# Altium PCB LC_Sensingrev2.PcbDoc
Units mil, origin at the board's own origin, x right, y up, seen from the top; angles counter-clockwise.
Board outline 1000 x 820 mil, 2 copper layers (Top Layer, Bottom Layer), stack 40 mil thick; 60 components, 18 nets, 111 pads, 7 vias.
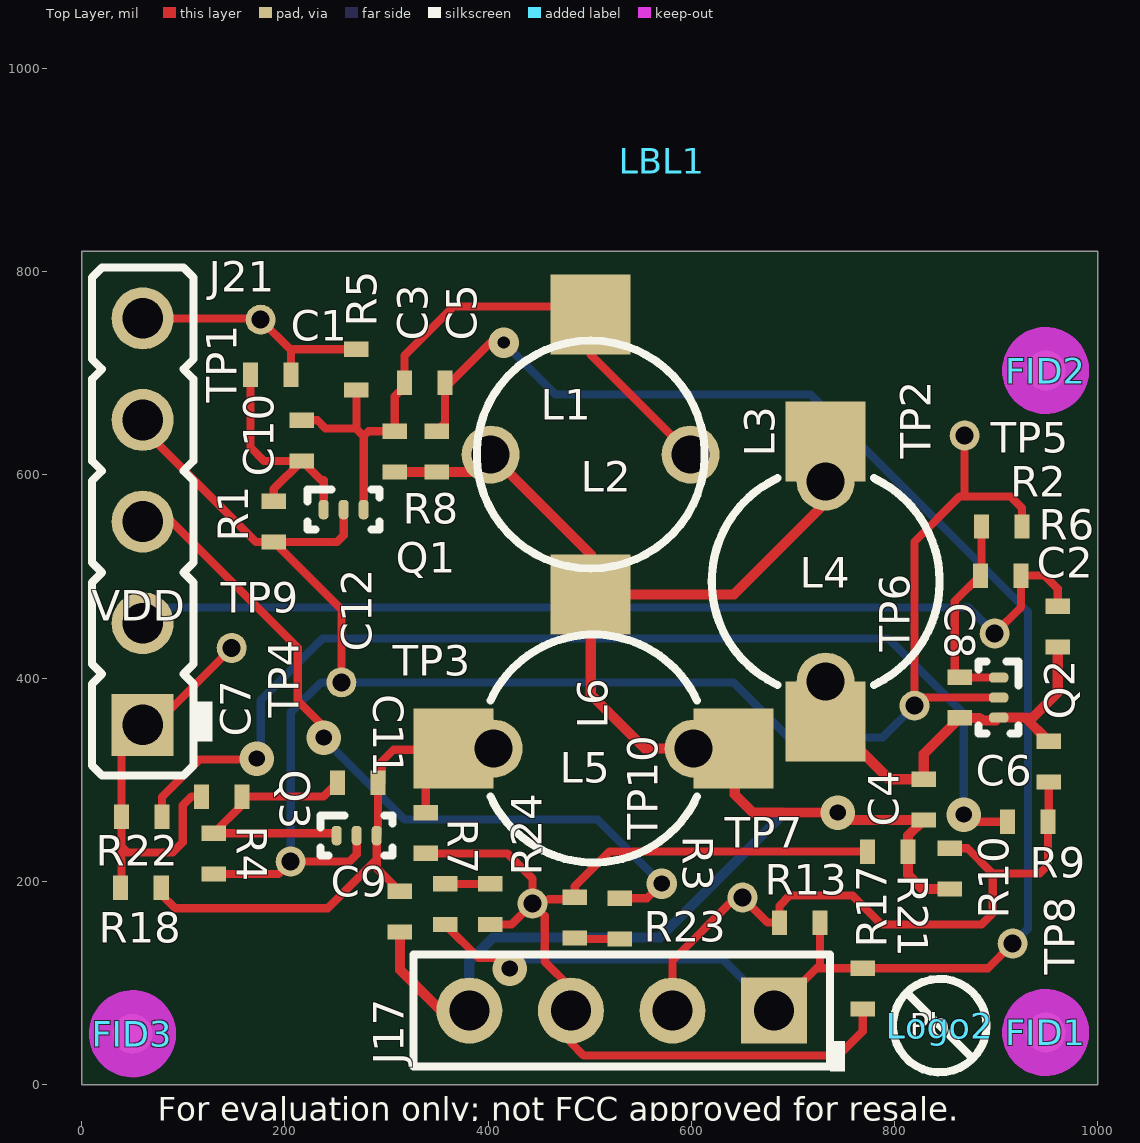
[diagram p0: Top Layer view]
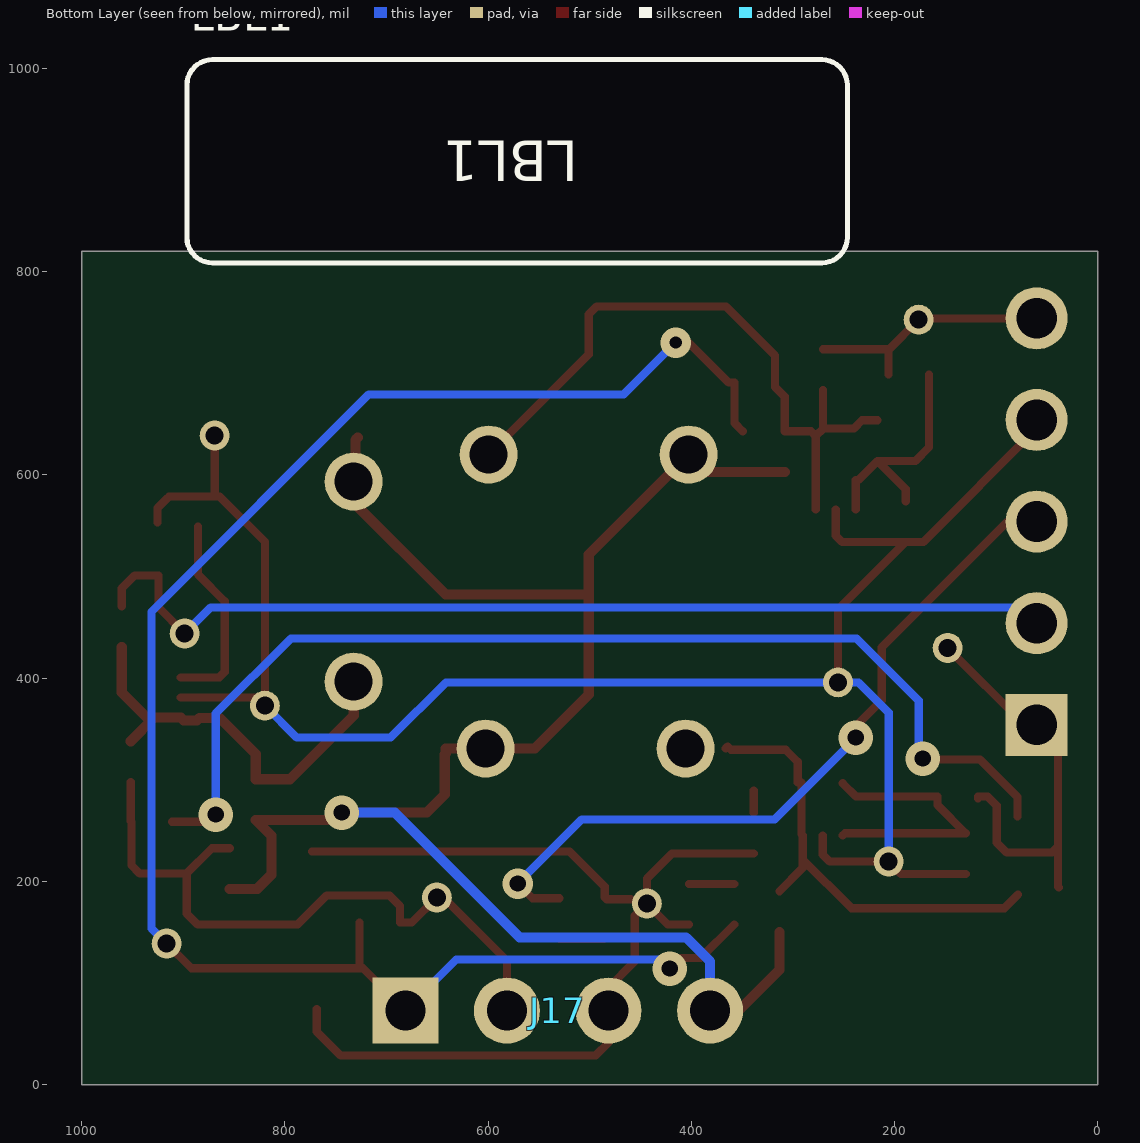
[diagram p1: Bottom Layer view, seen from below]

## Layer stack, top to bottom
Top Solder: solder mask 0.4, Solder Resist, Dk 3.5
Top Layer: signal copper 1.4
Dielectric1: core 37.2, FR-4, Dk 4.8
Bottom Layer: signal copper 1.4
Bottom Solder: solder mask 0.4, Solder Resist, Dk 3.5

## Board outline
0,0 1000,0 1000,820 0,820

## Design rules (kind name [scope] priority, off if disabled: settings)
AcuteAngle [All] p1: minimum=4.50000000000000E+0001 checktracksonly=FALSE
AssemblyTestPointUsage [All] p1: valid=2
BoardOutlineClearance BoardOutlineClearance_MountingHoles [OnCopper and InComponentClass('Mounting Holes')] p1: gap=20
BoardOutlineClearance BoardOutlineClearance_Poly [OnCopper and IsPoly] p2: gap=20
BoardOutlineClearance [OnCopper and Not InComponentClass('Logo') and not InComponentClass('FiducialMark') and not InRegion(1000,500,4000,800) and not InPoly] p3: gap=22
Clearance Clearance_Keepouts [((IsTrack Or IsArc) And Not InPoly) And IsFree and IsKeepOut vs ((IsTrack Or IsArc) And Not InPoly) And IsFree and IsKeepOut] p1: gap=0
Clearance Clearance_Poly [InPolygon] p2: gap=25
Clearance [All] p3: gap=7.87
ComponentClearance ComponentClearance_MountingHoles_FiducialMarks [InComponentClass('Mounting Holes') vs InComponentClass('FiducialMark')] p1: gap=3.94 collisioncheckmode=3 verticalgap=3.94 showdistances=FALSE
ComponentClearance ComponentClearance_Shunt [InComponentClass('Header') vs InComponentClass('Shunt')] p2: gap=0 collisioncheckmode=3 verticalgap=0 showdistances=FALSE
ComponentClearance ComponentClearance_Logo [InComponentClass('Logo')] p3: gap=10 collisioncheckmode=3 verticalgap=10 showdistances=TRUE
ComponentClearance ComponentClearance_ScrewToNut [(HasFootprint('NY PMS 440 0025 PH')) vs (HasFootprint('Keystone_1902C'))] p4: gap=5 collisioncheckmode=3 verticalgap=10 showdistances=FALSE
ComponentClearance ComponentClearance_MountingHoles [InComponentClass('Mounting Holes')] p5: gap=250 collisioncheckmode=3 verticalgap=100000 showdistances=FALSE
ComponentClearance ComponentClearance_SmallPassives [HasFootprint('0201*') or HasFootprint('0402*') or HasFootprint('0508') or HasFootprint('0603*') or HasFootprint('0612') or HasFootprint('0805*') or HasFootprint('0815*') or HasFootprint('0830*') or HasFootprint('1206*') or HasFootprint('1210*') or HasFootprint('1808*') or HasFootprint('1812*') or HasFootprint('1825*') or HasFootprint('2010*') or HasFootprint('2220*') or HasFootprint('2225*') or HasFootprint('2512*') or HasFootprint('2728*') or HasFootprint('3518*') vs HasFootprint('0201*') or HasFootprint('0402*') or HasFootprint('0508') or HasFootprint('0603*') or HasFootprint('0612') or HasFootprint('0805*') or HasFootprint('0815*') or HasFootprint('0830*') or HasFootprint('1206*') or HasFootprint('1210*') or HasFootprint('1808*') or HasFootprint('1812*') or HasFootprint('1825*') or HasFootprint('2010*') or HasFootprint('2220*') or HasFootprint('2225*') or HasFootprint('2512*') or HasFootprint('2728*') or HasFootprint('3518*')] p6: gap=14.96 collisioncheckmode=3 verticalgap=10 showdistances=FALSE
ComponentClearance ComponentClearance_THtoSMT [IsThruComponent vs IsSMTComponent] p7: gap=10 collisioncheckmode=3 verticalgap=10 showdistances=FALSE
ComponentClearance ComponentClearance_THtoTH [IsThruComponent vs IsThruComponent] p8: gap=12 collisioncheckmode=3 verticalgap=12 showdistances=FALSE
ComponentClearance [All] p9: gap=7 collisioncheckmode=3 verticalgap=7 showdistances=FALSE
DiffPairsRouting [All] p1: maxlimit=100 minlimit=10 mostfreqgap=10 toplayer_minwidth=15 toplayer_maxwidth=15 toplayer_prefwidth=15 bottomlayer_minwidth=15 bottomlayer_maxwidth=15 bottomlayer_prefwidth=15 maxuncoupledlength=1000
FabricationTestPointUsage TestPointUsage [All] p1: valid=2 allowmultiple=FALSE
FabricationTestpoint Testpoint [All] p1: side=3 testpointundercomponent=TRUE minsize=40 maxsize=100 preferedsize=60 minholesize=0 maxholesize=40 preferedholesize=32 testpointgrid=1 allowsidetop=TRUE allowsidebottom=TRUE usegrid=TRUE gridtolerance=0.01
FanoutControl Fanout_LCC [IsLCC] p1: bgadir=Out bgaviamode=Centered fanoutstyle=Auto fanoutdirection=Alternating viagrid=1 // Fanout_LCC (Default Rule)
FanoutControl Fanout_BGA [IsBGA] p2: bgadir=Out bgaviamode=Centered fanoutstyle=Auto fanoutdirection=Alternating viagrid=1 // Fanout_BGA (Default Rule)
FanoutControl Fanout_Default [All] p4: bgadir=Out bgaviamode=Centered fanoutstyle=Auto fanoutdirection=Alternating viagrid=1 // Fanout_Default (Default Rule)
FanoutControl Fanout_Small [(CompPinCount < 5)] p5: bgadir=Out bgaviamode=Centered fanoutstyle=Auto fanoutdirection=OutThenIn viagrid=1 // Fanout_Small (Default Rule)
HoleSize [All] p1: absolutevalues=TRUE maxlimit=251 minlimit=7.87 maxpercent=80.000 minpercent=20.000
MinimumAnnularRing MinimumAnnularRing_ThermalPadVias [IsVia and InAnyComponent] p1: minimumring=5.91
MinimumAnnularRing [All] p2: minimumring=5.91
MinimumSolderMaskSliver MinimumSolderMaskSliver_Logo [InComponentClass('Logo') vs InComponentClass('Logo')] p1: minsoldermaskwidth=0.7
MinimumSolderMaskSliver [All] p2: minsoldermaskwidth=3.94
PlaneConnect [All] p1: planeconnectstyle=Relief reliefexpansion=10 reliefentries=4 reliefconductorwidth=10 reliefairgap=10
PolygonConnect [All] p1: connectstyle=Relief reliefconductorwidth=10 reliefentries=4 polygonreliefangle="90 Angle" airgapwidth=10
RoutingVias ThermalPadVias [IsVia and InAnyComponent] p1: holewidth=7.87 width=19.68 viastyle="Through Hole" minholewidth=7.87 minwidth=19.68 maxholewidth=12.99 maxwidth=23.62
RoutingVias [All] p2: holewidth=16 width=34 viastyle="Through Hole" minholewidth=7.87 minwidth=26 maxholewidth=40 maxwidth=65
SilkToBoardRegionClearance [Not ((IsComment or IsDesignator) And (Hide <> 'False')) and not InRegion(1000,500,4000,800)] p1:
SilkToSilkClearance SilkToSilkClearance_Pb-FreeLogo [(HasFootprint('Pb-Free_Overlay_Medium') OR HasFootprint('Pb-Free_Overlay_Small')) vs (HasFootprint('Pb-Free_Overlay_Medium') OR HasFootprint('Pb-Free_Overlay_Small'))] p1: silktosilkclearance=0
SilkToSilkClearance [All] p2: silktosilkclearance=2
SilkToSolderMaskClearance SilkToComponentPadClearance [IsPad and InAnycomponent] p1: minsilkscreentomaskgap=5 clearancetoexposedcopper=TRUE
SilkToSolderMaskClearance "Silk to Solder Mask Opening" [All] p2: minsilkscreentomaskgap=4 clearancetoexposedcopper=FALSE
SolderMaskExpansion [All] p1: expansion=1.97
UnRoutedNet [All] p1 off:
Width [All] p1: maxlimit=100 minlimit=6 preferedwidth=10 checkconnectedcopper=TRUE
14 further rules are at their usual default settings.

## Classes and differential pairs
component class LC_PMOSrev2: C1 C2 C3 C4 C5 C6 C7 C8 C9 C10 C11 C12 J17 J21 L1 L2 L3 L4 L5 L6 Q1 Q2 Q3 R1 R2 R3 R4 R5 R6 R7 R8 R9 R10 R13 R17 R18 R21 R22 R23 R24 TP1 TP2 TP3 TP4 TP5 TP6 TP7 TP8 TP9 TP10
component class Label: LBL1
component class AssemblyNote: ZZ1 ZZ2 ZZ3 ZZ4
component class FiducialMark: FID1 FID2 FID3
component class LC_Hardwarerev2: FID1 FID2 FID3 LBL1 Logo2 Logo3 ZZ1 ZZ2 ZZ3 ZZ4
component class Header: J17 J21

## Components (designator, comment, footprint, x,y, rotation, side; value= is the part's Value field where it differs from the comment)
C1 "GRM155R61A473KA01D" 0402S 186.02,698.82 r0 top
C2 "GRM155R61A473KA01D" 0402S 904.53,500.98 r0 top
C3 "GRM1555C1H101JA01D" 0402S 308.07,623.03 r270 top
C4 "GRM1555C1H101JA01D" 0402S 828.74,280.51 r270 top
C5 "GRM1555C1H101JA01D" 0402S 337.6,690.94 r180 top
C6 "GRM1555C1H101JA01D" 0402S 951.77,317.91 r90 top
C7 "GRM155R61A473KA01D" 0402S 137.8,283.46 r180 top
C8 "GRM155R71H332KA01D" 0402S 864.42,380.95 r270 top
C9 "GRM1555C1H101JA01D" 0402S 313.23,170.28 r270 top
C10 "GRM155R71H332KA01D" 0402S 216.67,633.86 r90 top
C11 "GRM1555C1H101JA01D" 0402S 338.58,247.58 r90 top
C12 "GRM155R71H332KA01D" 0402S 271.65,297.24 r0 top
FID1 "Fiducial" Fiducial10-20 948.82,51.18 r0 top
FID2 "Fiducial" Fiducial10-20 948.82,702.76 r0 top
FID3 "Fiducial" Fiducial10-20 50,50 r0 top
J17 "PEC04SAAN" SULLINS_PEC04SAAN 531.5,72.83 r180 bottom locked
J21 "PEC05SAAN" Sullins_PxC05SAAN 60.04,554.13 r90 top locked
L1 "BV1935" BV1935 500.98,620.08 r90 top
L2 "BV1935" BV1935 732.29,495.08 r270 top
L3 "GT1128-0" GT1128-0 500.98,620.08 r0 top
L4 "GT1128-0" GT1128-0 732.29,495.07 r270 top
L5 "GT1128-0" GT1128-0 503.94,330.71 r180 top
L6 "BV1935" BV1935 503.94,330.71 r180 top
LBL1 "Size: 0.65\" x 0.20 \"" Label_650x200 571.44,908.73 r0 top
Logo2 "Pb-Free Symbol" Pb-Free_Overlay_Small 844.49,58.07 r0 top
Logo3 "FCC disclaimer" FCC_disclaimer 2350,3380 r0 top
Q1 "CSD23285F5" YJK0003A 257.87,565.94 r0 top
Q2 "CSD23285F5" YJK0003A 902.56,380.91 r270 top
Q3 "CSD23285F5" YJK0003A 270.67,245.08 r0 top
R1 "CRCW04021M00JNED" 0402S 188.98,554.13 r270 top
R2 "CRCW04021M00JNED" 0402S 905.51,549.21 r0 top
R3 "CRCW04021M00JNED" 0402S 485.24,164.37 r270 top
R4 "CRCW04021M00JNED" 0402S 129.92,227.36 r270 top
R5 "CRCW04020000Z0ED" 0402S 270.4,703.74 r90 top
R6 "CRCW04020000Z0ED" 0402S 960.63,450.79 r90 top
R7 "CRCW04021M00JNED" 0402S 357.73,177.58 r90 top
R8 "CRCW04021M20JNED" 0402S 349.41,623.03 r90 top
R9 "CRCW04021M00JNED" 0402S 931.1,258.71 r180 top
R10 "CRCW04021M20JNED" 0402S 854.33,212.6 r90 top
R13 "CRCW04020000Z0ED" 0402S 706.69,159.45 r180 top
R17 "CRCW04020000Z0ED" 0402S 768.7,94.49 r270 top
R18 "CRCW04020000Z0ED" 0402S 58.27,193.9 r180 top
R21 "CRCW04021M20JNED" 0402S 793.31,229.33 r180 top
R22 "CRCW04020000Z0ED" 0402S 59.06,263.78 r0 top
R23 "CRCW04020000Z0ED" 0402S 529.73,163.39 r270 top
R24 "CRCW04020000Z0ED" 0402S 402.22,177.58 r90 top
TP1 "TP_H0.45P0.75" TP_H045P075#1 214.57,487.2 r90 top
TP2 "TP_H0.45P0.75" TP_H045P075#2 898.62,443.9 r90 top
TP3 "TP_H0.45P0.75" TP_H045P075#3 275.59,695.87 r90 top
TP4 "TP_H0.45P0.75" TP_H045P075#2 205.71,219.49 r90 top
TP5 "TP_H0.45P0.75" TP_H045P075#2 869.08,638.78 r90 top
TP6 "TP_H0.45P0.75" TP_H045P075#2 819.72,372.87 r90 top
TP7 "TP_H0.45P0.75" TP_H045P075#2 650.48,184.06 r90 top
TP8 "TP_H0.45P0.75" TP_H045P075#2 916.34,138.78 r90 top
TP9 "TP_H0.45P0.75" TP_H045P075#4 147.68,449.8 r90 top
TP10 "TP_H0.45P0.75" TP_H045P075#2 443.73,178.15 r90 top
ZZ1 "This Assembly Note is for PCB labels only" AssemblyNoteLabel 185,3938 r0 top
ZZ2 "These assemblies are ESD sensitive, ESD precautions shall be observed." AssemblyNote 185,3829.11 r0 top
ZZ3 "These assemblies must be clean and free from flux and all contaminants. Use of no clean flux is not acceptable." AssemblyNote 185,3740.56 r0 top
ZZ4 "These assemblies must comply with workmanship standards IPC-A-610 Class 2, unless otherwise specified." AssemblyNote 185,3652 r0 top

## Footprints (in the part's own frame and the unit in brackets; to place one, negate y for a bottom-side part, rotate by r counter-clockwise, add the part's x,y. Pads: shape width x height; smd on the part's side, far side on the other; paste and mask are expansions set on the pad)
0402S [mil] "Based on C0402S footprint from PADS legacy"
  rect 15x24 smd: 1(-20,0) 2(20,0)
  body extent -22,-12 22,12, height 24
AssemblyNote [mil] "Assembly Note"
AssemblyNoteLabel [mil] "Assembly Note for PCB Labels"
BV1935 [mm] "SMD, 2-Leads, Dia 5.7mm"
  rect 2x2 smd: 1(-3.5,0) 2(3.5,0)
  silkscreen extent -2.52,-2.85 2.52,2.85, body extent -2.85,-2.85 2.85,2.85, height 4.7
FCC_disclaimer [mil]
Fiducial10-20 [mm]
  round 1 smd mask+0.5: 1(0,0)
  Top Layer keep-out circle w1.178: c0,0 r0.5
GT1128-0 [mm] "TH, 2-Leads, Body 6.4x5.7mm, Pin Spacing 5mm"
  round 1.45 hole 0.95: 1(-2.5,0) 2(2.5,0)
  silkscreen extent -2.58,-2.85 2.58,2.85, body extent -2.85,-2.85 2.85,2.85, height 6.2
Label_650x200 [mil] "Thermal Transfer Label"
  round 1 on Mech14: 0(0,0)
  body extent -325,-100 325,100, height 1
Pb-Free_Overlay_Small [mil]
  silkscreen extent -46,-46 46,46
SULLINS_PEC04SAAN [mm] "SULLINS"
  rect 1.65x1.65 hole 1: 1(-3.81,0)
  round 1.65 hole 1: 2(-1.27,0) 3(1.27,0) 4(3.81,0)
  body extent -5.21,-1.33 5.21,1.33, height 8.38
Sullins_PxC05SAAN [mm] "Header, 2.54mm, 5x1, TH"
  rect 1.55x1.55 hole 1.016: 1(-5.08,0)
  round 1.55 hole 1.016: 2(-2.54,0) 3(0,0) 4(2.54,0) 5(5.08,0)
  silkscreen extent -6.35,-1.75 6.35,1.27, body extent -6.35,-1.27 6.35,1.27, height 5.84
TP_H045P075#1 [mm] "TP_H0.45P0.75"
  round 0.75 hole 0.45: 1(6.746,0.975)
TP_H045P075#2 [mm] "TP_H0.45P0.75"
  round 0.75 hole 0.45: 1(0,0)
TP_H045P075#3 [mm] "TP_H0.45P0.75"
  round 0.75 hole 0.45: 1(-7.62,0.508)
TP_H045P075#4 [mm] "TP_H0.45P0.75"
  round 0.75 hole 0.45: 1(-0.508,0)
YJK0003A [mm] "SMD, 3-Leads, Body 1.49x0.73mm"
  rrect50% 0.2x0.39 on Top Paste: 1(-0.525,0) 2(0,0) 3(0.525,0)
  rrect80% 0.25x0.49 smd paste-0.15 mask-0.05: 1(-0.5,0) 2(0,0) 3(0.5,0)
  silkscreen extent -0.9,-0.5 0.9,0.5, body extent -0.75,-0.37 0.74,0.36, height 0.35

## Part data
C1 C2 C7: "CAP, CERM, 0.047 µF, 10 V, +/- 10%, X5R, 0402"
C3 C4 C5 C6 C9 C11: "CAP, CERM, 100 pF, 50 V, +/- 5%, C0G/NP0, 0402"
C8 C10 C12: "CAP, CERM, 3300 pF, 50 V, +/- 10%, X7R, 0402"
FID1 FID2 FID3: "Fiducial mark.  There is nothing to buy or mount."
J17: "Header, 100mil, 4x1, Tin, TH"
J21: "Header, 2.54mm, 5x1, Tin, TH"
L1 L2 L6: "Inductor, Wirewound, 200 µH, 1.9 ohm, SMD"
L3 L4 L5: "Inductor, 235µH, TH"
LBL1: library part THT-14-423-10, "Thermal Transfer Printable Labels, 0.650\" W x 0.200\" H - 10,000 per roll"
Logo2: library part Pb-Free
Logo3: library part FCC_disclaimer, "FCC_disclaimer"
Q1 Q2 Q3: "MOSFET, P-CH, -12 V, -3.3 A, YJK0003A (PICOSTAR-3)"
R1 R2 R3 R4 R7 R9: "RES, 1.0 M, 5%, 0.063 W, 0402"
R5 R6 R13 R17 R18 R22 R23 R24: "RES, 0, 5%, 0.063 W, 0402"
R8 R10 R21: "RES, 1.2 M, 5%, 0.063 W, 0402"
TP1 TP2 TP3 TP4 TP5 TP6 TP7 TP8 TP9 TP10: "Testpoint"
ZZ1: library part AssemblyNoteLabel
ZZ2 ZZ3 ZZ4: library part AssemblyNote

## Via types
v1: diameter 34, hole 16, Top Layer to Bottom Layer, 5 vias
v2: diameter 30, hole 16, Top Layer to Bottom Layer, 1 vias
v3: diameter 30, hole 12, Top Layer to Bottom Layer, 1 vias

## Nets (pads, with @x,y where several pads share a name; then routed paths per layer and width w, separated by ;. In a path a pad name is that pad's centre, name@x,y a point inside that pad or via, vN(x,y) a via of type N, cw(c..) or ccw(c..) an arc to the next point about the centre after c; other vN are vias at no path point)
BIAS1: R7.2 R24.2 | length 44.5
  Top Layer w8: R7.2 R24.2
BIAS2: R9.2 R22.2 | length 1081.4
  Top Layer w8: R22.2 79.06,282.99 115.95,319.88 v1@172.24,319.88 ; v1@172.24,318.9 v1@172.24,319.88 ; v1@172.24,320.87 v1@172.24,319.88 ; v1(868.11,265.75) 875.15,258.71 R9.2
  Bottom Layer w8: v1(172.25,320.88) 176.18,324.81 176.18,377.95 237.2,438.98 794.17,438.98 868.11,365.04 v1(868.11,265.75)
BIAS3: R3.2 R23.2 | length 43.5
  Top Layer w8: R3.2@486.22,143.39 R23.2
DVDD: J21.4 Q1.2@257.87,565.94 Q2.2@902.56,380.91 Q3.2@270.67,245.08 R1.2 R2.2 R4.2 TP3.1 TP4.1 TP5.1 TP6.1 | length 1873
  Top Layer w8: J21.4 60.04,645.67 171.57,534.13 R1.2 R1.2@189.15,533.96 ; R4.2 193.58,207.36 TP4.1 263.78,219.49 270.67,226.38 Q3.2@270.67,245.08 ; TP3.1 255.59,467.52 R1.2@189.15,533.96 ; Q1.2@257.87,565.94 257.87,540.35 251.48,533.96 R1.2@189.15,533.96 ; TP6.1@820.87,363.19 TP6.1@825.14,367.46 ; 869.08,583.65 TP5.1 ; Q2.2@902.56,380.91 827.76,380.91 TP6.1 819.72,534.29 864.17,578.74 914.12,578.74 ; 915.72,577.14 925.51,567.35 R2.2@925.51,553.15
  Bottom Layer w8: TP4.1 205.71,366.14 235.43,395.87 TP3.1 641.54,395.87 695.87,341.54 788.39,341.54 TP6.1 ; TP6.1@819.72,382.87 TP6.1@820.87,382.87
FLOW_OUTP: C5.1 J17.1 R7.1 R8.2 R13.1 R17.1 TP8.1 | length 1743.5
  Top Layer w8: R8.2 357.6,651.22 C5.1 363.19,690.94 402.56,730.32 v3(415.35,730.32) ; R7.1 390.78,124.52 410.94,124.52 v1(421.28,114.18) ; J17.1@690.28,81.62 723.15,114.49 R17.1 892.05,114.49 TP8.1 ; 726.69,118.03 R13.1
  Bottom Layer w8: v3(415.35,730.32) 466.54,679.13 717.52,679.13 931.27,465.38 931.27,153.71 TP8.1 ; v1(421.28,114.18) 421.26,118.11 426.18,123.03 631.3,123.03 J17.1
FLOW_OUTP2: C6.1 J17.2 R9.1 R10.2 R13.2 TP7.1 | length 669.2
  Top Layer w8: J17.2 581.5,121.85 643.7,184.06 TP7.1 675.09,159.45 R13.2 686.69,175.87 696.85,186.02 758.86,186.02 787.4,157.48 885.83,157.48 896.65,168.31 896.65,207.68 ; R10.2 871.73,232.6 896.65,207.68 ; C6.1 951.77,259.38 R9.1 951.1,215.87 942.91,207.68 896.65,207.68
FLOW_OUTP3: C11.1 J17.3 R3.1 R17.2 R21.2 R24.1 TP10.1 | length 1006.7
  Top Layer w8: C11.1 419.08,227.58 443.73,202.92 TP10.1 ; R24.1 423.16,157.58 TP10.1 ; 459.65,182.4 483.27,182.4 R3.1 485.24,194.88 519.69,229.33 R21.2 ; R17.2 768.7,52.17 745.08,28.54 718.95,28.54 718.89,28.48 644.1,28.48 644.04,28.54 599.93,28.54 599.87,28.48 563.13,28.48 563.07,28.54 494.09,28.54 481.5,41.14 J17.3 481.5,95.27 455.71,121.06 455.71,166.17 TP10.1
FLOW_TRIG1: C1.2 J21.5 R5.2 TP1.1 | length 235.9
  Top Layer w8: J21.5@69.88,754.13 174.84,754.13 TP1.1 206.02,722.95 C1.2 ; 207.68,723.74 R5.2
FLOW_TRIG2: C2.2 J21.2 R6.2 TP2.1 | length 982.2
  Top Layer w8: TP2.1 924.53,469.8 C2.2 947.83,500.98 960.63,488.19 R6.2
  Bottom Layer w8: J21.2 75.39,469.49 873.03,469.49 TP2.1
FLOW_TRIG3: C7.2 J21.1 R18.2 R22.1 TP9.1 | length 420.2
  Top Layer w8: R18.2 39.06,194.69 39.06,234.25 ; J21.1@39.06,333.15 R22.1 39.06,234.25 ; J21.1 J21.1@72.01,354.13 ; J21.1@76.65,354.13 J21.1@72.01,354.13 ; C7.2@117.79,281.5 C7.2 108.27,283.47 99.41,274.61 99.41,238.19 89.57,228.35 44.96,228.35 39.06,234.25 ; TP9.1 J21.1@72.01,354.13
  Bottom Layer w8: J21.1@39.06,333.15 J21.1
FLOW_TRIG4: J21.3 R23.1 | length 743
  Top Layer w8: J21.3 88.58,554.13 212.6,430.12 212.6,377.95 238.19,352.36 v1(238.19,341.54) ; R23.1 556.42,183.39 v2(570.87,197.83)
  Bottom Layer w8: v1(238.19,341.54) 238.19,340.55 317.91,260.83 507.87,260.83 v2(570.87,197.83)
GND: C3.2 C4.2 C9.2 J17.4 L1.1 L2.1 L3.1 L4.1 L5.1 L6.1 R8.1 R10.1 R21.1 | length 1817.4
  Top Layer w10: C3.2 R8.1 385.5,603.03 L3.1 500.98,521.66 L1.1 ; C9.2 313.23,112.95 353.35,72.84 J17.4 ; L2.1@728.35,636.81 730.63,634.53 730.63,571.18 641.74,482.29 L1.1 ; R10.1 827.09,192.6 813.31,206.38 R21.1 813.31,245.08 C4.2 751.3,260.51 v1(744.09,267.72) 660.43,267.72 642.72,285.43 642.72,324.8 641.73,325.79 L6.1 554.13,330.71 500.98,383.86 L1.1
  Bottom Layer w10: J17.4 381.5,121.06 405.12,144.68 568.9,144.68 691.93,267.72 v1(744.09,267.72)
NetC1_1: C1.1 C10.1 Q1.1@238.19,565.94 R1.1 | length 237.4
  Top Layer w8: C1.1 166.02,627.28 179.45,613.86 C10.1 ; R1.1 188.98,586.16 C10.1 ; Q1.1@238.19,565.94 238.19,595.12 235.41,595.12 C10.1
NetC2_1: C2.1 C8.1 Q2.1@902.56,400.59 R2.1 | length 199.6
  Top Layer w8: R2.1 885.51,501.97 C2.1 859.25,475.71 859.25,443.9 859.25,406.12 C8.1 864.78,400.59 Q2.1@902.56,400.59
NetC3_1: C3.1 C5.2 C10.2 L1.2 L3.2 Q1.3@277.56,565.94 R5.1 | length 673.2
  Top Layer w8: C10.2 231.97,653.86 239.99,645.84 269.96,645.84 277.56,638.24 ; 270.4,646.28 R5.1 ; Q1.3@277.56,565.94 277.56,638.24 ; L3.2 500.98,718.51 L1.2 493.11,765.75 365.83,765.75 317.6,717.52 C5.2 317.6,686.69 308.07,677.17 C3.1 282.35,643.03 277.56,638.24
NetC4_1: C4.1 C6.2 C8.2 L2.2 L4.2 Q2.3@902.56,361.22 R6.1 | length 417.8
  Top Layer w10: L4.2 732.29,363.19 794.96,300.51 C4.1 828.74,325.28 C8.2 883.81,360.95 886.5,358.27 899.61,358.27 902.56,361.22 928.47,361.22 ; C6.2 928.47,361.22 ; R6.1 960.63,385.83 936.02,361.22 928.47,361.22
NetC7_1: C7.1 C12.1 Q3.1@250.99,245.08 R4.1 | length 268.3
  Top Layer w8: Q3.1@250.99,245.08 248.7,247.36 R4.1 157.79,275.23 C7.1 237.87,283.47 C12.1@250.99,296.58
NetC9_1: C9.1 C11.2 C12.2 L5.2 L6.2 Q3.3@290.36,245.08 R18.1 | length 472.9
  Top Layer w8: R18.1@78.27,187.22 91.9,173.59 242.49,173.59 290.36,221.46 ; Q3.3@290.36,245.08 290.36,221.46 ; Q3.3@291.65,246.38 C12.2 ; C12.2@295.28,297.24 295.28,317.74 307.09,329.56 361.05,329.56 364.17,332.68 L6.2 ; C9.1 290.36,213.15 290.36,221.46 ; C11.2 338.58,289.37
pads on no net: FID1.1 FID2.1 FID3.1 LBL1.0 Q1.1@237.2,565.94 Q1.2@257.87,565.94 Q1.3@278.54,565.94 Q2.1@902.56,401.58 Q2.2@902.56,380.91 Q2.3@902.56,360.24 Q3.1@250,245.08 Q3.2@270.67,245.08 Q3.3@291.34,245.08

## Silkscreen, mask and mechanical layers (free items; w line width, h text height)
Top Overlay:
  text "1" at 739.84,8036.5 h40
  text "2" at 3235.5,8036.5 h40
  text "3" at 5724.84,8036.5 h40
  text "4" at 8231.51,8036.5 h40
  text "5" at 10730.5,8036.5 h40
  text "6" at 13235.5,8036.5 h40
  text "A" at -416.5,6893.5 h40
  text "A" at 14383.5,6893.5 h40
  text "DESIGN INFORMATION" at 12378.02,6201 h40
  text "MIN. TRACK WIDTH:" at 11733.46,6021 h40
  text "8" at 12829.7,6021 h40
  text "MIL" at 12984.46,6021 h40
  text "MIN. CLEARANCE:" at 11733.46,5889 h40
  text "0.2" at 12769.7,5889 h40
  text "mm" at 12984.46,5889 h40
  text "MIN. VIA PAD SIZE:" at 11733.46,5757 h40
  text "24" at 12799.71,5757 h40
  text "MIL" at 12984.46,5757 h40
  text "0.05mm (2MIL)" at 12428.46,5615.29 h40
  text "MINIMUM ANNULAR RING" at 11404.23,5611 h40
  text "EXTERNAL" at 13136.46,5611 h40
  text "PER" at 11604.23,5493 h40
  text "IPC-D-275 CLASS 2 LEVEL C" at 11824.23,5493 h40
  text "MIL, HOLES" at 13312.46,5380.71 h40
  text "+/-" at 12920,5380 h40
  text "+/-" at 13774,5380 h40
  text "REGISTRATION TOLERANCES:" at 11404.23,5375 h40
  text "METAL" at 12604,5375 h40
  text "5" at 13180.2,5375 h40
  text "3" at 14013.2,5375 h40
  text "MIL" at 14129.46,5375 h40
  text "+/-" at 13774,5262 h40
  text "HOLE SIZE TOLERANCE (UNLESS OTHERWISE SPECIFIED):" at 11404.23,5257 h40
  text "3" at 14013.2,5257 h40
  text "MIL" at 14129.46,5257 h40
  text "MATERIAL:" at 11329.46,5047.54 h40
  text "FR-4 High Tg" at 12315.9,4907.21 h40
  text "FR-408" at 11750.46,4898.64 h40
  text "OTHER" at 13238.46,4898.64 h40
  text "X" at 12161,4895 h40
  text "62 MIL (1.6mm) +/-10%" at 12070.56,4735.92 h40
  text "THICKNESS:" at 11404.23,4731.64 h40
  text "X" at 11942.4,4731.64 h40
  text "OTHER" at 13355.46,4731.64 h40
  text "TOLERANCE:" at 11404.23,4573.64 h40
  text "X" at 12243.53,4573.64 h40
  text "ANSI IPC-6012 TYPE 3 CLASS 2" at 12430.48,4573.64 h40
  text "B" at -416.5,4513.5 h40
  text "B" at 14383.5,4513.5 h40
  text "OTHER +/-" at 12430.46,4417.64 h40
  text "BOW & TWIST:" at 11404.23,4260.64 h40
  text "X" at 12243.53,4260.64 h40
  text "ANSI IPC-6012 TYPE 3 CLASS 2" at 12430.48,4260.64 h40
  text "OTHER +/-" at 12430.46,4102.13 h40
  text "DRILLING:" at 11329.46,3963.64 h40
  text "REFERENCE:" at 11404.23,3846.64 h40
  text "X" at 12052.46,3846.64 h40
  text "AS SHOWN" at 12239.46,3846.64 h40
  text "X" at 12953.46,3846.64 h40
  text "NC_DRILL FILES" at 13090.46,3846.64 h40
  text "PTH COPPER THICKNESS:" at 11404.23,3688.64 h40
  text "X" at 12534.46,3688.64 h40
  text "20-30 um" at 12671.46,3688.64 h40
  text "OTHER" at 13388.46,3688.64 h40
  text "BOARD FINISH:" at 11329.46,3529.64 h40
  text "SILKSCREEN:" at 11484.68,3411.64 h40
  text "X" at 12433.46,3411.64 h40
  text "TOP" at 12559.46,3411.64 h40
  text "X" at 12943.46,3411.64 h40
  text "BOTTOM" at 13070.46,3411.64 h40
  text "SILKSCREEN COLOR:" at 11484.68,3244.64 h40
  text "X" at 12432.42,3244.64 h40
  text "WHITE" at 12559.46,3244.64 h40
  text "OTHER" at 13070.46,3244.64 h40
  text "CERTIFICATION:" at 2339.31,3149.74 h40
  text "X" at 12563.42,3085.44 h40
  text "GREEN" at 12690.46,3085.44 h40
  text "OTHER" at 13308.46,3085.44 h40
  text "SOLDER RESIST COLOR:" at 11484.68,3074.64 h40
  text "X" at 2690.82,2915.24 h40
  text "X" at 12563.42,2915.44 h40
  text "MATTE" at 12690.46,2915.44 h40
  text "SEMI-GLOSS" at 13308,2914.8 h40
  text "X" at 3504.87,2755.74 h40
  text "RoHS" at 3641.82,2755.74 h40
  text "IMMERSION GOLD (ENIG)" at 12390.46,2726.92 h40
  text "ENEPIG" at 13728,2723.64 h40
  text "SURFACE FINISH:" at 11329.46,2722.64 h40
  text "X" at 12203.51,2722.64 h40
  text "IMM. TIN/SILVER OR EQUIV" at 11659,2565.64 h40
  text "OTHER" at 13090.46,2565.64 h40
  text "ARRAY/PANEL:" at 11329.46,2386.64 h40
  text "CUT AND TRIM PER M1 BOARD OUTLINE" at 12390.46,2382.35 h40
  text "ADDITIONAL REQUIREMENTS:" at 2339.31,2296.74 h40
  text "N.C. ROUTE" at 12390.46,2230.64 h40
  text "X" at 13069.46,2230.64 h40
  text "V. SCORE" at 13256.46,2230.64 h40
  text "MICROSECTION:" at 2414.08,2181.74 h40
  text "YES" at 3319.82,2181.74 h40
  text "C" at -416.5,2138.5 h40
  text "C" at 14383.5,2138.5 h40
  text "MATERIALS AND WORKMANSHIP FOR ALL PCBS" at 12054.46,2093.64 h40
  text "BARE BOARD ELEC. TEST:" at 2414.08,2022.74 h40
  text "NONE" at 3719.82,2022.74 h40
  text "TO MEET OR EXCEED THE REQUIREMENTS OF:" at 12054.46,1995.64 h40
  text "ANSI IPC-A-600F CLASS ->" at 11819.96,1859.13 h40
  text "X" at 13459.02,1859.13 h40
  text "2" at 13577.96,1859.14 h40
  text "1" at 13262.96,1857.64 h40
  text "3" at 13931.96,1857.64 h40
  text "OTHER" at 13276.36,1699.64 h40
  text "PER ORDER" at 13673.42,1699.64 h40
  text "ALL BOARDS MUST MEET OR EXCEED UL94-V0 REQUIREMENTS." at 11357,1534 h40
  text "PCB MUST BEAR THE UL94V-0 UL REGISTERED MATERIAL ID NUMBER" at 11357,1414 h40
  text "REQUIRED" at 13171.46,969.49 h40
  text "X" at 13044.46,966.64 h40
  text "PER ORDER" at 13763.46,966.64 h40
  text "VDD" at 9.84,456.69 h30
  text "PROJECT TITLE:" at 11343.5,277.5 h40
  text ".PRJ_Title" at 11393.5,144.17 h40
  text "DESIGNED FOR:" at 11343.5,-23.5 h40
  text ".PRJ_Customer" at 11393.5,-163.5 h40
  text "D" at -416.5,-231.5 h40
  text "D" at 14383.5,-231.5 h40
  text "COMPONENTS MARKED 'DNP' SHOULD NOT BE POPULATED." at 1153.5,-318.5 h40
  text "COMPONENTS MARKED 'DNP' SHOULD NOT BE POPULATED." at 6102,-318 h40
  text "FILE NAME:" at 11343.5,-323.5 h40
  text "ASSEMBLY VARIANT:" at 1153,-434 h40
  text ".VariantName" at 2189,-434 h40
  text ".VariantName" at 5058,-434 h40
  text "ASSEMBLY VARIANT:" at 6097,-434 h40
  text ".PCB_File_Name_No_Path" at 11393.5,-443.5 h40
  text "Texas Instruments (TI) and/or its licensors do not warrant the accuracy or completeness of this specification" at 6374,-605.34 h40
  text "ENGINEER:" at 11343.5,-613.5 h40
  text "LAYOUT BY:" at 12848.5,-613.5 h40
  text "PCB VIEWED FROM TOP SIDE" at -228.5,-655.67 h40
  text "ALL ARTWORK VIEWED FROM TOP SIDE" at -228.5,-655.67 h40
  text ".VersionControl_RevNumber" at 1035.5,-656.17 h40
  text "SVN REV:" at 1541.5,-656.17 h40
  text ".PCB_Rev" at 2088,-656.17 h40
  text "BOARD #:" at 2248,-655.67 h40
  text "BOARD #:" at 2248,-655.67 h40
  text "REV:" at 2379.5,-656.17 h40
  text ".PRJ_Number" at 2793.5,-655.67 h40
  text ".PRJ_Number" at 2793.5,-655.67 h40
  text ".PRJ_Number" at 3224,-656.17 h40
  text "REV:" at 3638,-655.67 h40
  text "REV:" at 3638,-655.67 h40
  text "BOARD #:" at 3769.5,-656.17 h40
  text ".PCB_Rev" at 3929.5,-655.67 h40
  text ".PCB_Rev" at 3929.5,-655.67 h40
  text "SVN REV:" at 4476,-655.67 h40
  text "SVN REV:" at 4476,-655.67 h40
  text ".VersionControl_RevNumber" at 4982,-655.67 h40
  text ".VersionControl_RevNumber" at 4982,-655.67 h40
  text "PCB VIEWED FROM BOTTOM SIDE" at 6246,-656.17 h40
  text "or any information contained therein. TI and/or its licensors do not warrant that this design will meet" at 6329.01,-718 h40
  text ".PRJ_Engineer" at 11393.5,-768.49 h40
  text ".PCB_Layout" at 12899,-768.49 h40
  text "the specifications, will be suitable for your application or fit for any particular purpose, or will operate in" at 6329.01,-830.67 h40
  text "LAYER NAME =" at -228.5,-858.49 h40
  text ".Layer_Name" at 577,-858.49 h40
  text ".Layer_Name" at 577,-858.49 h40
  text ".Layer_Name" at 577,-858.49 h40
  text ".Layer_Name" at 577,-858.49 h40
  text ".Layer_Name" at 577,-858.49 h40
  text ".Layer_Name" at 577,-858.49 h40
  text ".Layer_Name" at 577,-858.49 h40
  text ".Layer_Name" at 577,-858.49 h40
  text ".Layer_Name" at 577,-858.49 h40
  text ".Layer_Name" at 577,-858.49 h40
  text ".Layer_Name" at 577,-858.49 h40
  text ".Layer_Name" at 577,-858.49 h40
  text ".Layer_Name" at 577,-858.49 h40
  text ".Layer_Name" at 577,-858.49 h40
  text ".Layer_Name" at 577,-858.49 h40
  text ".Layer_Name" at 577,-858.49 h40
  text ".Layer_Name" at 577,-858.49 h40
  text ".Layer_Name" at 577,-858.49 h40
  text ".Layer_Name" at 577,-858.49 h40
  text ".Layer_Name" at 577,-858.49 h40
  text ".Layer_Name" at 577,-858.49 h40
  text ".Layer_Name" at 577,-858.49 h40
  text ".Layer_Name" at 577,-858.49 h40
  text ".Layer_Name" at 577,-858.49 h40
  text ".Layer_Name" at 577,-858.49 h40
  text ".Layer_Name" at 577,-858.49 h40
  text "TID #:" at 2248,-859 h40
  text "TID #:" at 2248,-859 h40
  text ".TID" at 2793.5,-859 h40
  text ".TID" at 2793.5,-859 h40
  text ".TID" at 3224,-859.5 h40
  text "TID #:" at 3769.5,-859.5 h40
  text "ALTIUM DESIGNER VERSION:" at 12848.5,-923.5 h40
  text "an implementation. TI and/or its licensors do not warrant that the design is production worthy. You should" at 6329.01,-943.33 h40
  text "completely validate and test your design implementation to confirm the system functionality for your application." at 6374,-1056 h40
  text ".print_Scale" at 11393.5,-1056.83 h40
  text ".Application_BuildNumber" at 12899,-1056.83 h40
  text "PLOT NAME =" at -228.5,-1064.34 h40
  text "PLOT NAME =" at -228.5,-1064.34 h40
  text ".plot_File_Name" at 577,-1064.34 h40
  text ".plot_File_Name" at 577,-1064.34 h40
  text "GENERATED    :" at 2250,-1064.34 h40
  text "GENERATED    :" at 2250,-1064.34 h40
  text ".Print_Date" at 3119.5,-1064.34 h40
  text ".Print_Date" at 3119.5,-1064.34 h40
  text ".Print_Time" at 3848.5,-1064.34 h40
  text ".Print_Time" at 3848.5,-1064.34 h40
  text "TEXAS INSTRUMENTS" at 5113,-1064.34 h40
  text "TEXAS INSTRUMENTS" at 5113,-1064.34 h40
  text "TEXAS INSTRUMENTS" at 904.5,-1064.84 h40
  text ".Print_Time" at 2169,-1064.84 h40
  text ".Print_Date" at 2898,-1064.84 h40
  text "GENERATED    :" at 3767.5,-1064.84 h40
  text ".plot_File_Name" at 5440.5,-1064.84 h40
  text "PLOT NAME =" at 6246,-1064.84 h40
  text "1" at 739.84,-1263.5 h40
  text "2" at 3235.5,-1263.5 h40
  text "3" at 5724.84,-1263.5 h40
  text "4" at 8231.51,-1263.5 h40
  text "5" at 10730.5,-1263.5 h40
  text "6" at 13235.5,-1263.5 h40
M1 Board Outline:
  lines w10: 0,3.94 0,820 1000,820 1000,3.94 0,3.94
M2 Board Dimensions:
  rectangle: 125,-400 500,-275
  rectangle: 0,-275 125,-150
  lines w7: 0,-275 1000,-275 ; 125,-400 125,-150 ; 250,-400 250,-150 ; 500,-400 500,-150 ; 750,-400 750,-150 ; 0,-400 0,-150 1000,-150 1000,-400 0,-400
M5 Assembly Top:
  lines w10: -292,-930.17 6308,-930.17 ; -292,-726.83 6310,-726.83 ; -292,-523.5 -292,-1133.5 3713,-1133.5 6310,-1133.5 6310,-523.5 -291.5,-523.5 -291.5,-1133.5 1284,-1133.5 ; 2173,-1133.5 2173,-523.5 ; 3440,-726.83 3440,-523.5 ; 4280,-726.83 4280,-523.5 ; 4902,-1140 4902,-937.17
M6 Assembly Bottom:
  lines w10: -292.5,-727.33 6309.5,-727.33 ; -290.5,-930.67 6309.5,-930.67 ; 1115.5,-1140.5 1115.5,-937.67 ; 1737.5,-727.33 1737.5,-524 ; 2577.5,-727.33 2577.5,-524 ; 3844.5,-1134 3844.5,-524 ; 4733.5,-1134 6309,-1134 6309,-524 -292.5,-524 -292.5,-1134 2304.5,-1134 6309.5,-1134 6309.5,-524
M9 Title Sheet:
  drawing of 57 lines, arcs and shapes, not listed
M10 Fab Notes:
  drawing of 173 lines, arcs and shapes, not listed
M11 Gerber Information:
  lines w10: -292,-930.17 6308,-930.17 ; -292,-726.83 6310,-726.83 ; -292,-523.5 -292,-1133.5 3713,-1133.5 6310,-1133.5 6310,-523.5 -291.5,-523.5 -291.5,-1133.5 1284,-1133.5 ; 2173,-1133.5 2173,-523.5 ; 3440,-726.83 3440,-523.5 ; 4280,-726.83 4280,-523.5 ; 4902,-1140 4902,-937.17
M12 Stackup:
  drawing of 332 lines, arcs and shapes, not listed
  text "Layer" at 6555.03,7744.02 h60
  text "Name" at 6964.94,7744.02 h60
  text "Material" at 7894.68,7744.02 h60
  text "Thickness" at 8754.45,7744.02 h60
  text "Constant" at 9404.29,7744.02 h60
  text "Board Layer Stack" at 9974.15,7744.02 h60
  text "1" at 6555.03,7624.02 h60
  text "Top Overlay" at 6964.94,7624.02 h60
  text "2" at 6555.03,7504.02 h60
  text "Top Solder" at 6964.94,7504.02 h60
  text "Solder Resist" at 7894.68,7504.02 h60
  text "0.40mil" at 8754.45,7504.02 h60
  text "3.5" at 9404.29,7504.02 h60
  text "3" at 6555.03,7384.02 h60
  text "Top Layer" at 6964.94,7384.02 h60
  text "Copper" at 7894.68,7384.02 h60
  text "1.40mil" at 8754.45,7384.02 h60
  text "4" at 6555.03,7264.02 h60
  text "Dielectric1" at 6964.94,7264.02 h60
  text "FR-4" at 7894.68,7264.02 h60
  text "37.20mil" at 8754.45,7264.02 h60
  text "4.8" at 9404.29,7264.02 h60
  text "5" at 6555.03,7144.02 h60
  text "Bottom Layer" at 6964.94,7144.02 h60
  text "Copper" at 7894.68,7144.02 h60
  text "1.40mil" at 8754.45,7144.02 h60
  text "6" at 6555.03,7024.02 h60
  text "Bottom Solder" at 6964.94,7024.02 h60
  text "Solder Resist" at 7894.68,7024.02 h60
  text "0.40mil" at 8754.45,7024.02 h60
  text "3.5" at 9404.29,7024.02 h60
  text "7" at 6555.03,6904.02 h60
  text "Bottom Overlay" at 6964.94,6904.02 h60
Drill Drawing:
  circle w10: c1507.69,651.54 r22.07
  lines w10: 1485.62,232.19 1529.76,232.19 1529.76,276.34 1485.62,276.34 1485.62,232.19 ; 1485.62,331.51 1485.62,342.55 1496.66,353.58 1485.62,364.62 1485.62,375.66 1496.66,375.66 1507.69,364.62 1518.73,375.66 1529.76,375.66 1529.76,364.62 1518.73,353.58 1529.76,342.55 1529.76,331.51 1518.73,331.51 1507.69,342.55 1496.66,331.51 1485.62,331.51 ; 1485.62,474.98 1529.76,474.98 1507.69,430.83 1485.62,474.98 ; 1485.62,541.19 1496.66,541.19 1496.66,530.15 1518.73,530.15 1518.73,541.19 1529.76,541.19 1529.76,563.26 1518.73,563.26 1518.73,574.3 1496.66,574.3 1496.66,563.26 1485.62,563.26 1485.62,541.19 ; 1485.62,739.83 1496.66,739.83 1507.69,728.79 1518.73,739.83 1529.76,739.83 1518.73,750.86 1529.76,761.9 1518.73,761.9 1507.69,772.94 1496.66,761.9 1485.62,761.9 1496.66,750.86 1485.62,739.83
  lines w12: 1444.98,202.4 4556.19,202.4 ; 1444.98,798.32 4556.19,798.32 ; 1760.46,103.08 1760.46,897.64 ; 2077.56,103.08 2077.56,897.64 ; 2699.2,103.08 2699.2,897.64 ; 2943.39,103.08 2943.39,897.64 ; 3303.63,103.08 3303.63,897.64 ; 4012.1,103.08 4012.1,897.64 ; 1444.98,103.08 4556.19,103.08 4556.19,897.64 1444.98,897.64 1444.98,103.08
  text "Symbol" at 1504.57,828.11 h72
  text "Quantity" at 1790.26,828.11 h72
  text "Finished Hole Size" at 2107.35,828.11 h72
  text "Plated" at 2728.99,828.11 h72
  text "Hole Type" at 2973.19,828.11 h72
  text "Drill Layer Pair" at 3333.43,828.11 h72
  text "Hole Tolerance" at 4041.9,828.11 h72
  text "1" at 1790.26,728.79 h60
  text "12.00mil (0.305mm)" at 2107.35,728.79 h60
  text "PTH" at 2728.99,728.79 h60
  text "Round" at 2973.19,728.79 h60
  text "Top Layer - Bottom Layer" at 3333.43,728.79 h60
  text "6" at 1790.26,629.47 h60
  text "16.00mil (0.406mm)" at 2107.35,629.47 h60
  text "PTH" at 2728.99,629.47 h60
  text "Round" at 2973.19,629.47 h60
  text "Top Layer - Bottom Layer" at 3333.43,629.47 h60
  text "10" at 1790.26,530.15 h60
  text "17.72mil (0.450mm)" at 2107.35,530.15 h60
  text "PTH" at 2728.99,530.15 h60
  text "Round" at 2973.19,530.15 h60
  text "Top Layer - Bottom Layer" at 3333.43,530.15 h60
  text "6" at 1790.26,430.83 h60
  text "37.40mil (0.950mm)" at 2107.35,430.83 h60
  text "PTH" at 2728.99,430.83 h60
  text "Round" at 2973.19,430.83 h60
  text "Top Layer - Bottom Layer" at 3333.43,430.83 h60
  text "4" at 1790.26,331.51 h60
  text "39.37mil (1.000mm)" at 2107.35,331.51 h60
  text "PTH" at 2728.99,331.51 h60
  text "Round" at 2973.19,331.51 h60
  text "Top Layer - Bottom Layer" at 3333.43,331.51 h60
  text "5" at 1790.26,232.19 h60
  text "40.00mil (1.016mm)" at 2107.35,232.19 h60
  text "PTH" at 2728.99,232.19 h60
  text "Round" at 2973.19,232.19 h60
  text "Top Layer - Bottom Layer" at 3333.43,232.19 h60
  text "32 Total" at 1790.26,132.87 h60

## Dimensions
0,0 to 1000,0 on M2 Board Dimensions
0,0 to 0,820 on M2 Board Dimensions
0,-400 to 1000,-400 on M2 Board Dimensions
